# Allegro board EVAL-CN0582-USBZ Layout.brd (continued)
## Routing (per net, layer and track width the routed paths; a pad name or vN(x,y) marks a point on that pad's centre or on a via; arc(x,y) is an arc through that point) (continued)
P5V_SUPPLY: length 73.1
  TOP w0.305: A8.7 73.53,98.23 73.08,97.78 C213.1 ; R228.1 v1(101.85,99.82) ; U32.2 86.54,96.72 C239.1 ; A5.7 v1(99.06,91.51) ; A14.7 v1(98.95,96.72) ; R310.1 C239.1 ; C239.1 v1(85.7,96.77) ; C182.1 72.96,89.97 A7.7
  TOP w0.508: C182.1 C183.2 v1(70.99,89.91) ; v1(71.13,97.78) C215.2 C213.1 ; v1(38.67,60.01) v1(37.97,60.01) 37.98,60 R8.1
  L3_SIG w0.508: 38.23,60.96 38.23,60.26 v1(37.97,60.01) 37.97,60.71 38.23,60.96 ; 38.23,60.96 38.61,61.34 ; 38.61,61.34 38.61,60.07 v1(38.67,60.01) ; 38.61,61.34 38.61,64.64 39.37,65.4 39.37,70.99 41.53,73.15 46.4,73.15 48.01,74.76 48.01,82.93 53.47,88.39 53.47,96.69 53.42,96.74 53.42,100.41 v1(54.23,101.22)
  BOTTOM w0.305: v1(98.95,96.72) 99.01,96.77 C235.1 C237.2 v1(99.7,98.54) ; v1(99.06,91.51) 99.12,91.51 99.18,91.57 C190.2 C187.1
  vias: v1(54.23,101.98) v1(54.99,101.98) v1(54.99,101.22)
V1P2_SUPPLY: length 30.1
  TOP w0.203: R225.1 31.79,14.44 31.8,14.43 ; U1.H1 47.1,16.15 v2(47.24,16) ; U1.F11 45.34,24.94 45.34,25.4 v2(44.96,25.78) ; U1.C3 v2(42.68,17.97) ; 32.16,14.2 32.18,14.17 33.17,14.17 33.32,14.33 33.32,16.76 32.65,17.44 R226.2 ; v1(48.39,25.78) 47.91,25.3 47.91,24.8 U1.J11 ; U1.L5 49.54,19.94 v2(50.44,19.94) ; U1.E9 v2(44.28,23.6) ; U1.B10 v2(41.88,24.4) ; U1.L7 v2(50.16,21.59)
  TOP w0.508: E9.2 31.11,21.59 v1(30.99,21.46) ; C138.2 v1(52.58,17.58) ; C22.1 v1(50.56,27.3) ; C136.1 v1(47.48,14.23) ; v1(52.45,14.48) 52.46,14.49 C20.2 ; v1(44.83,27.05) 44.56,27.33 44.54,27.33 44.28,27.58 44.28,27.6 43.82,28.07 C18.2 ; v1(52.58,18.6) 53.32,18.6 C24.1 ; C21.2 v1(40.01,25.91) ; C19.1 v1(40.01,26.92) ; E8.2 v1(34.8,13.59)
  BOTTOM w0.305: v2(44.28,23.6) 44.28,24.43 C135.1
  BOTTOM w0.457: C23.2 46.98,16.12 47.1,16 v2(47.24,16)
  BOTTOM w0.508: E6.2 31.5,20.96 v1(30.99,21.46) ; C139.1 v1(39.37,15.11)
  vias: v1(31.6,13.18) v1(31.6,12.55) v1(31.62,11.89)
3P3V_SUPPLY: length 265.2
  TOP w0.152: v1(9.27,8.76) 9.27,8.76
  TOP w0.203: U1.C11 v2(42.68,25.2) ; U1.H11 47.1,25.89 v1(47.37,26.16) ; U1.F1 45.5,16.09 v2(45.41,16) ; 50.74,23.19 U1.L9 ; U1.B1 v2(41.88,16.37) ; R111.2 v1(7.38,63.5) ; U1.E3 v2(45.11,18.8)
  TOP w0.305: v1(68.96,43.05) 68.96,42.93 69.46,42.43 C281.1 69.6,42.15 U39.1 ; R247.2 38.47,68.97 38.75,68.7 U12.2 ; v1(29.57,35.43) 29.59,35.43 29.85,35.17 C294.1 30.36,35.18 U42.5 ; 50.74,23.19 50.75,23.18 v1(51.12,23.18)
  TOP w0.406: v1(13.84,89.42) C274.1 12.96,89.53 U37.2
  TOP w0.508: v1(53.6,2.42) R192.2 R191.2 ; R337.2 v1(11.68,91.44) ; R246.2 v1(35.92,67.94) ; v1(19.06,94.48) C273.1 C288.2 16.85,94.65 Y6.4 ; R315.2 v1(13.09,80.77) ; v1(13.09,82.8) C245.1 12.25,82.86 U33.5 ; 56.91,27.17 P8.3 ; P8.3 57.53,25.04 ; P8.3 57.53,29.29 ; U2.8 53.97,34.33 C205.1 v1(54.99,33.27) ; R355.2 58.17,45.58 58.25,45.5 58.25,44.93 58.25,44.92 58.25,44.88 v1(58.04,44.68) ; v1(20.19,13.97) 20.19,13.97 19.99,13.77 19.99,13.58 19.94,13.53 R196.2 ; R284.1 v1(91.29,10.08) ; R207.2 v1(23.11,1.02) ; 12.86,19.01 E15.2 ; E15.2 14.82,19.01 ; E15.2 13.84,19.86 ; R194.2 v1(64.9,36.7) ; R236.2 v1(30.92,10.79) R206.2 ; 14.87,18.96 C277.1 ; C277.1 16.37,18.96 ; C277.1 15.62,19.69 ; R89.2 22.22,100.2 v1(22.22,101.09) ; C144.1 C148.2 47.51,26.3 v1(47.37,26.16) ; R237.1 R238.1 v1(35.19,10.79) ; R193.2 v1(64.9,34.42) ; v1(56.01,21.84) 55.88,21.84 55.8,21.77 55.72,21.77 55.62,21.67 55.41,21.67 55.4,21.67 54.83,21.67 54.83,21.67 R179.2 ; R356.1 v1(38.87,54.74) ; C147.1 51.68,23.74 v1(51.12,23.18) ; R229.2 v1(21.97,1.02) ; C151.1 C155.2 v2(45.41,16) ; v1(14.74,90.54) C290.2 C289.1 15.02,88.37 15.02,86.93 U41.5 ; Y4.4 Y4.1 65.57,83.81 C176.1 C267.2 v1(63.09,83.81) ; R250.1 v1(41.4,80.64) ; R197.1 v1(64.9,35.56) ; R199.2 v1(21.08,13.97) ; v1(17.95,23.41) C257.2 C258.2 17.65,26.21 C255.1 17.65,28.33 v1(17.53,28.45) ; v1(13.59,60.71) 13.84,60.45 R294.2 ; v1(8.6,76.93) C286.2 8.6,76.16 C285.1 8.58,75.07 U3.5 ; R352.1 v1(37.66,62.11) ; R210.1 v1(50.67,38.35) ; R357.2 v1(53.85,9.14) ; R244.2 v1(35.54,65.71) ; R240.2 v1(47.26,70.74) ; v1(30.23,43.43) 30.52,43.73 E16.1 ; R230.2 v1(20.83,1.01) ; R211.2 v1(50.67,37.08) ; R320.2 v1(67.69,40.39) ; R283.1 v1(91.42,31.03) ; R149.1 v1(55.38,48.64) ; v1(56.22,44.23) 56.18,44.26 56.18,44.48 55.74,44.92 R255.1 ; R279.1 v1(91.42,69.54) ; R331.2 v1(17.02,97.03) ; R313.1 v1(8.52,68.46) ; C246.2 v1(13.09,81.79) ; U38.5 5.65,85.4 5.96,85.1 C275.1 C276.2 v1(8.15,85.1) ; E17.1 v1(32.68,52.62) ; v1(47.37,68.71) 47.12,68.45 R242.2 ; 9.27,8.76 R208.1 ; R209.1 v1(50.67,35.69) ; R205.2 23.89,13.2 v1(24.38,13.69) ; v1(35.79,68.97) C16.2 R247.2 ; R200.2 v1(22.22,13.97) ; R275.2 v1(22.73,14.6) ; R280.1 v1(91.29,48.59)
  L3_SIG w0.508: v1(91.29,10.08) 90.63,10.74 90.63,17.68 92.46,19.51 92.46,20.83 91.42,21.87 v1(91.42,31.03) 91.44,31.05 91.44,35.05 90.04,36.45 90.04,43.69 91.29,44.93 v1(91.29,48.59) 91.31,48.61 91.31,54.1 92.09,54.88 92.09,59.68 91.42,60.35 v1(91.42,69.54) ; v1(39.52,27.62) 40.29,27.62 42.68,25.23 v2(42.68,25.2)
  L4_SIG w0.508: 31.62,5.68 31.62,6.86 ; 31.62,6.86 30.44,6.86 ; 31.62,6.86 31.62,8.04 ; 31.62,6.86 32.8,6.86 ; 34.63,75.82 P11.1 ; P11.1 35.81,77 ; P11.1 37,75.82 ; 35.81,79.54 P11.2 34.63,78.36 ; 39.08,4.32 40.26,4.32 ; 40.26,4.32 41.44,4.32 ; 40.26,4.32 40.26,3.14 ; 40.26,4.32 40.26,5.5 ; 45.34,6.86 46.52,6.86 ; 45.34,6.86 45.34,5.68 ; 45.34,6.86 44.16,6.86 ; 45.34,6.86 45.34,8.04 ; v1(51.12,23.18) 51.5,23.18 51.82,23.5 ; 40.01,28.7 40.01,28.24 39.52,27.76 v1(39.52,27.62) ; 47.12,29.08 47.12,26.42 v1(47.37,26.16)
  BOTTOM w0.203: v1(17.53,28.45) 17.88,28.45 18.06,28.27 U35.4 ; U36.12 11.93,22.39 12.07,22.25 12.19,22.25 C256.1
  BOTTOM w0.254: U16.9 57.72,46.23 57.69,46.2 56.9,46.2 C140.1 C143.1
  BOTTOM w0.305: C162.1 45.09,18.82 v2(45.11,18.8)
  BOTTOM w0.356: C201.2 C200.1 42.68,26.02 v2(42.68,25.2)
  BOTTOM w0.508: R100.2 v1(6.73,20.45) ; E4.2 44.74,40.17 44.58,40 v1(44.58,39.62) ; v1(54.61,46.46) 54.72,46.35 54.81,46.35 55.08,46.08 C143.1 ; R1.2 v1(14.95,23.5) ; R287.2 27.55,66.16 v1(28.83,67.44) ; C170.2 C162.1 ; E7.2 38.53,26.63 v1(39.52,27.62) ; R317.2 v1(7.5,25.59) ; v1(14.83,22.14) C259.2 13.58,21.84 C256.1 ; C197.2 41.88,16.11 v2(41.88,16.37) 41.88,17.04 C194.1 ; v1(91.29,10.08) 86.85,5.64 56.82,5.64 v1(53.6,2.42) ; E3.1 v1(46.04,48.22) ; R79.2 v1(14.95,24.64)
  vias: v1(15.11,20.83) v1(15.11,20.07) v1(16.13,20.83) v1(16.13,20.07) v1(16.89,20.07) v1(16.89,19.3) v1(56.39,29.21) v1(56.39,28.45) v1(56.39,27.81) v1(56.39,27.05) v1(56.39,26.29) v1(56.39,25.65)
10P5V_SUPPLY: length 16.3
  TOP w0.152: TP49.1 39.5,101.35 39.5,101.3 v1(39.54,101.3)
  TOP w0.508: R97.2 v1(27.93,99.81)
  BOTTOM w0.305: v1(39.54,101.3) 38.48,102.36 28.24,102.36 27.93,102.06 v1(27.93,99.81)
4332_A: length 5.9
  TOP w0.203: P11.5 40.27,75.19 R252.1 40.65,73.15 U12.20
4332_B: length 9
  TOP w0.203: U12.19 41.15,73.42 R252.2 41.27,73.78 42.16,74.68 42.16,77.09 P11.6
4332_CS: length 64.2
  TOP w0.203: v1(42.67,61.85) 42.41,62.11 R245.1
  L3_SIG w0.152: v1(42.67,61.85) 41.15,60.32 41.15,52.46 42.83,50.77 43.17,50.77 44.42,49.52 44.42,47.52 42.92,46.02 41.16,46.02 41,45.86 41,44.26 48.01,37.25 48.01,35.36 52.98,30.39 52.98,29.1 54.89,27.19 54.89,24.89 55.28,24.5 55.28,21.1 56.08,20.29 56.54,20.29 57.56,19.28 57.56,15.94 57.4,15.79 v1(57.4,14.99)
  BOTTOM w0.152: R214.2 55.37,14.99 v1(57.4,14.99)
4332_EN: length 110.2
  TOP w0.203: R353.2 R246.1 37.93,68.16 v1(38.48,68.16) 39.48,68.16 U12.3
  L3_SIG w0.152: v1(33.53,58.67) 33.15,58.67 24.26,49.78 24.26,43.05 27.56,39.75 27.56,33.53 26.16,32.13 25.7,32.13 25.15,31.58 25.15,31.12 24.13,30.1 24.13,28.58 21.41,25.86 21.41,24.12 19.88,22.58 19.88,15.3 17.48,12.9 17.48,3.23 18.03,2.67 27.43,2.67 30.35,5.59 30.35,7.62 34.42,11.68 36.62,11.68 37.13,12.19 38.23,12.19 v1(38.73,11.68)
  BOTTOM w0.152: TP30.1 38.73,9.27 v1(38.73,11.68) 39.03,11.98 R270.2
  BOTTOM w0.203: v1(33.53,58.67) 33.53,59.94 37.85,64.26 37.85,67.53 v1(38.48,68.16)
4332_GPIO1: length 83.5
  TOP w0.203: U12.11 43.3,61.72 42.89,61.32 37.24,61.32 v1(36.96,61.04)
  L3_SIG w0.152: v1(45.87,11.68) 46.4,12.22 47.3,12.22 47.6,12.52 50.78,12.52 51.22,12.96 53.18,12.96 56.57,16.35 56.57,18.87 56.13,19.3 55.63,19.3 54.28,20.65 54.28,24.09 53.9,24.48 53.9,26.78 51.54,29.14 50.94,29.14 49.78,30.3 49.78,30.48 49.28,30.99 48.64,30.99 47.75,30.1 45.65,30.1 42.13,33.62 42.13,36.31 38.68,39.76 38.68,47.24 39.62,48.18 39.62,57.4 38.85,58.18 38.3,58.18 36.45,60.03 36.45,60.54 36.95,61.04 v1(36.96,61.04)
  BOTTOM w0.152: R215.2 45.87,12.01 v1(45.87,11.68)
4332_GPIO2: length 80.3
  TOP w0.152: v1(46.59,11.62) 46.59,12.3 R216.2
  TOP w0.203: U12.12 v1(44.18,67.19)
  L3_SIG w0.152: v1(44.18,67.19) 44.18,64.59 40.49,60.89 40.49,52.18 42.55,50.11 42.89,50.11 43.76,49.24 43.76,47.8 42.65,46.68 40.85,46.68 40.34,46.17 40.34,43.97 43.56,40.74 43.56,38.69 43.61,38.64 43.61,38.38 44.1,37.89 44.23,37.89 44.74,37.38 44.8,37.38 51.44,30.75 51.44,30.18 54.56,27.06 54.56,24.75 54.95,24.37 54.95,20.96 55.94,19.96 56.41,19.96 57.23,19.15 57.23,16.08 56.9,15.75 56.9,14.22 56.13,13.46 56.13,12.62 54.97,11.46 48.9,11.46 48.16,12.19 47.74,12.19 47.17,11.62 v1(46.59,11.62)
4332_GPIO3: length 82.2
  TOP w0.203: U12.13 43.33,67.73 44.41,67.73 44.83,67.31 44.83,62.71 43.05,60.93 37.69,60.93 37.08,60.32 v1(36.96,60.32)
  L3_SIG w0.152: v1(51.43,12.45) 51.57,12.32 53,12.32 56.9,16.21 56.9,19.01 56.27,19.63 55.81,19.63 54.61,20.83 54.61,24.23 54.23,24.62 54.23,26.92 51.07,30.08 51.07,30.65 44.66,37.05 44.6,37.05 44.09,37.56 43.97,37.56 43.28,38.25 43.28,38.51 43.23,38.56 43.23,39.36 40.01,42.59 40.01,46.31 40.71,47.01 42.51,47.01 43.43,47.93 43.43,49.11 42.76,49.78 42.42,49.78 40.16,52.04 40.16,57.34 38.99,58.51 38.65,58.51 36.96,60.2 v1(36.96,60.32)
  BOTTOM w0.203: R217.2 v1(51.43,12.45)
4332_INT: length 1.5
  TOP w0.203: R248.1 42.15,64.27 U12.10
4332_Y: length 12.7
  TOP w0.203: U12.17 42.53,70.34 45.23,73.04 45.23,74.7 44.7,75.22 44.7,77.09 P11.8 43.17,78.62 R250.2
4332_Z: length 6.2
  TOP w0.203: P11.7 43.06,75.45 R251.1 43.06,72.78 41.66,71.37 41.66,70.34 U12.18
7768_VCM: length 21.6
  TOP w0.203: 53.21,49.64 U18.59
  TOP w0.508: R117.1 v1(65.78,61.36) ; 53.21,49.64 53.74,50.16 55.12,50.16 57.51,52.55 v1(58.65,52.55)
  L3_SIG w0.508: v1(65.78,61.36) 64.9,60.49 64.9,58.05 59.41,52.55 v1(58.65,52.55)
-10P5_SUPPLY: length 18.9
  TOP w0.508: R95.2 v1(24.76,84.96)
  BOTTOM w0.305: v1(41.28,88.9) 30.99,88.9 28.63,86.54 26.34,86.54 v1(24.76,84.96)
AC_WAVE_SIGNAL: length 26.6
  TOP w0.305: A7.6 73.33,90.62 TP31.1 v1(71.75,91.19) ; U20.4 v1(78.02,95.34) ; R156.2 v1(82.43,89.79)
  L3_SIG w0.305: v1(82.43,89.79) 81.03,91.19 v1(71.75,91.19) 71.75,92.71 74.38,95.34 v1(78.02,95.34)
  BOTTOM w0.305: C292.2 82.05,89.41 v1(82.43,89.79)
AD5543_CS: length 82.4
  TOP w0.203: U20.8 75.04,93.39 75.69,92.74 75.69,86.73 76.07,86.35 v1(76.07,82.8) ; v1(60.45,30.84) 60.14,30.53 55.93,30.53 54.48,29.08 R133.1
  L3_SIG w0.152: v1(60.45,30.84) 59.36,31.93 59.36,45.12 58.34,46.13 58.34,46.41 58.34,49.13 57.48,50 57.48,53.05 59.38,54.94 60.15,54.94 61.44,56.24 61.44,71.6 70.36,80.52 73.79,80.52 v1(76.07,82.8)
AD5686_GAIN: length 25
  TOP w0.152: v1(48.51,40.72) 51.21,40.72 53.99,43.5 56.91,43.5 57.38,43.97 v1(58.04,43.97)
  BOTTOM w0.152: v1(58.04,43.97) 58.52,43.97 58.95,44.39 U16.8 ; R137.1 48.28,29.57 48.06,29.79 48.06,30.83 48.28,31.06 48.28,31.9 48.51,32.13 v1(48.51,40.72)
AD5686_LDAC: length 34.1
  L3_SIG w0.152: v1(62.48,22.48) 62.48,41.61 v1(60.27,43.81)
  BOTTOM w0.152: U16.7 59.45,44.64 v1(60.27,43.81) ; R166.1 55.28,20.32 62.48,20.32 62.59,20.42 62.59,20.42 62.99,20.82 62.99,21.98 62.49,22.48 v1(62.48,22.48)
AD5686_RSTSEL: length 40
  TOP w0.152: v1(62.38,20.93) 62.03,20.57 54.39,20.57 R144.1
  L3_SIG w0.152: v1(59.13,49.53) 63.04,45.62 63.04,21.46 62.51,20.93 v1(62.38,20.93)
  BOTTOM w0.203: U16.14 59.45,49.21 v1(59.13,49.53)
AD5686R_RST: length 39.1
  L3_SIG w0.152: v1(62.48,21.77) 62.28,21.97 62.27,21.97 61.98,22.27 61.98,23.35 60.1,25.23 60.1,30.42 59.03,31.49 59.03,44.98 58.01,46 58.01,48.25 v1(57.67,48.6)
  BOTTOM w0.152: R146.1 55.96,25.15 57.4,25.15 60.78,21.77 v1(62.48,21.77)
  BOTTOM w0.203: U16.13 57.82,48.48 57.7,48.6 v1(57.67,48.6)
AD5686R_SYNC: length 24.2
  TOP w0.152: v1(57.3,47.35) 57.31,47.36 R355.1
  L3_SIG w0.152: v1(57.3,47.35) 57.3,46.21 58.67,44.83 58.67,33.4 v1(58.42,33.15)
  BOTTOM w0.152: v1(58.42,33.15) 55.88,30.61 55.88,27.61 R136.1
  BOTTOM w0.203: v1(57.3,47.35) 57.38,47.35 57.5,47.23 U16.11
AD7768_CS: length 44.8
  TOP w0.152: U18.16 42.1,54.8 41.91,54.99 40.26,54.99 39.87,55.38 R356.2 ; R134.1 55.11,24.77 56.01,23.88 56.96,23.88 v1(57.4,23.43)
  TOP w0.203: U18.16 v1(42.1,52.78)
  L3_SIG w0.152: v1(57.4,23.43) 57.23,23.61 57.23,24.42 57.12,24.52 57.12,29.19 56.39,29.93 55.88,29.93 51.18,34.63 51.18,36.07 50.67,36.58 50.42,36.58 49.78,37.21 49.78,38.4 44.96,43.23 44.96,46.9 45.09,47.02 45.09,49.79 v1(42.1,52.78)
AD7768_DCLK: length 37
  TOP w0.203: U18.28 41.2,46.64 41.23,46.6 43.44,46.6 v1(44.45,45.59)
  L3_SIG w0.152: v1(44.45,45.59) 44.45,43.27 49.4,38.31 49.4,35.94 55.88,29.46 55.88,25.3 56.9,24.28 56.9,22.1 v1(57.15,21.84)
  BOTTOM w0.152: v1(57.15,21.84) 57.53,22.23 TP40.1 57.49,22.56 R140.1
AD7768_DRDY: length 38.7
  TOP w0.152: R141.1 55.45,22.72 55.8,23.07 55.84,23.07 55.88,23.11 v1(56.01,23.11)
  TOP w0.203: U18.29 41.87,46.14 v1(42.55,45.47) 42.55,44.51 41.22,43.18 TP39.1
  L3_SIG w0.152: v1(56.01,23.11) 55.61,23.52 55.61,24.64 55.22,25.03 55.22,29.14 48.73,35.64 48.73,38.05 43.6,43.18 43.6,44.53 42.67,45.47 v1(42.55,45.47)
AD7768_FILTER: length 2.9
  TOP w0.152: U18.11 44.6,55.13 44.6,55.13 44.6,55.4 45.47,56.26 R259.2
AD7768_FORMAT0: length 2.3
  TOP w0.203: U18.56 52.57,48.14 52.83,47.88
  TOP w0.254: R257.2 53.33,47.38 52.83,47.88
AD7768_MODE0: length 2.7
  TOP w0.203: U18.12 44.1,55.63 44.32,55.85 R263.2
AD7768_MODE1: length 2.8
  TOP w0.152: R262.2 43.18,55.54 43.6,55.13 U18.13
AD7768_MODE2: length 3
  TOP w0.203: U18.14 43.1,55.07 42.04,56.13 R261.2
AD7768_MODE3: length 3.8
  TOP w0.152: U18.15 42.6,54.94 42.17,55.37 41.28,55.37 40.89,55.75 R260.2
AD7768_RST: length 25.3
  TOP w0.203: v1(41.55,45.36) 41.51,45.36 41.23,45.64 U18.30
  L3_SIG w0.152: v1(53.54,30.1) 53.54,30.29 48.36,35.48 48.36,37.8 42.29,43.87 42.29,44.62 v1(41.55,45.36)
  BOTTOM w0.152: R147.1 55.24,29.85 54.99,30.1 53.55,30.1 v1(53.54,30.1)
AD7768_START: length 38.3
  TOP w0.203: U18.37 44.1,44.49 45.35,45.74 v1(46.5,45.74)
  L3_SIG w0.152: v1(58.67,22.23) 58.67,23.38 57.79,24.27 57.79,29.47 56.66,30.59 56.16,30.59 54.1,32.65 54.1,38.14 v1(46.5,45.74)
  BOTTOM w0.152: R152.1 56.81,23.66 57.09,23.94 57.85,23.94 58.67,23.11 v1(58.67,22.23)
AD9833_FSYNC: length 79.8
  TOP w0.203: v1(80.14,83.95) U19.8 ; v1(60.6,30.15) 60.5,30.05 56.21,30.05 54.35,28.19 R130.1
  L3_SIG w0.152: v1(80.14,83.95) 80.14,82.55 77.77,80.19 70.54,80.19 61.77,71.43 61.77,56.1 60.28,54.61 59.51,54.61 57.81,52.91 57.81,50.13 58.67,49.27 58.67,46.27 59.69,45.26 59.69,32.38 60.96,31.12 60.96,30.5 v1(60.6,30.15)
ADC_REF: length 20.9
  TOP w0.254: 47.1,55.34 U18.6 47.1,53.07 46.86,52.84 46.86,51.94 47.37,51.43 47.37,44.96 47.1,44.68 U18.43
  TOP w0.305: 47.1,55.34 47.1,55.63
  TOP w0.508: C157.2 48.32,59.22 VREF.1 ; C157.2 48.62,57.84 R139.2 R138.2 ; C157.2 48.32,57.72 47.89,57.28 R88.2 47.1,55.98 47.1,55.63
ADP5071_EN: length 119.5
  TOP w0.152: R126.1 51.58,29.74 51.94,30.1 v1(51.94,30.71) ; v1(25.65,91.32) 25.64,91.31 R98.2 20.82,91.31 20.19,90.68 20.19,88.77 v1(19.94,88.52)
  TOP w0.203: v1(26.04,94.72) 26.3,94.98 U15.9 26.3,97.21 26.1,97.41 23.49,97.41 22.61,98.3 R89.1 ; U15.11 v1(25.65,91.32)
  L3_SIG w0.152: v1(48.9,82.17) 49.28,81.79 49.28,75.31 45.47,71.5 45.47,67.76 44.58,66.87 44.58,64.52 40.82,60.76 40.82,52.32 42.69,50.44 43.03,50.44 44.09,49.38 44.09,47.66 42.79,46.35 40.98,46.35 40.67,46.03 40.67,44.1 43.89,40.88 43.89,38.83 43.94,38.78 43.94,38.52 44.24,38.22 44.37,38.22 44.87,37.71 44.94,37.71 v1(51.94,30.71)
  L3_SIG w0.203: v1(25.65,91.32) 25.65,94.33 v1(26.04,94.72)
  BOTTOM w0.152: v1(19.94,88.52) 19.94,84.84 21.84,82.93 48.13,82.93 v1(48.9,82.17)
ADP7142_ADJ: length 3.8
  TOP w0.203: R81.2 34.78,73.67 R277.1 33.73,73.65 R80.1 32.51,73.78 U11.2
BNC_CTRL: length 133.8
  TOP w0.305: U32.8 v1(89.45,97.37)
  L3_SIG w0.152: v1(40.17,10.45) 40.59,10.03 41.77,10.03 42.81,11.07 55.48,11.07 58.83,14.42 58.83,17.96 59.61,18.75 59.61,23.38 58.45,24.55 58.45,29.74 56.52,31.67 56.52,38.59 54.1,41.01 54.1,49.02 55.5,50.42 55.5,56.26 57.91,58.67 57.91,72.01 68.46,82.56 71.45,82.56 74.11,85.22 79.29,85.22 79.93,84.58 80.35,84.58 80.98,85.22 86.94,85.22 89.59,87.86 89.59,97.23 v1(89.45,97.37)
  BOTTOM w0.152: R273.2 v1(40.17,10.45)
CH0_COUP_OPT: length 129.4
  TOP w0.305: U22.15 v1(95.36,70.02) ; U22.6 v1(95.36,75.67)
  L3_SIG w0.152: v1(46.74,9.14) 47.75,9.14 47.88,9.02 53.29,9.02 53.34,8.97 53.34,8.93 53.64,8.64 54.06,8.64 54.36,8.93 54.36,8.97 54.41,9.02 77.72,9.02 83.69,3.05 88.14,3.05 92.58,7.49 92.58,16 94.49,17.91 94.49,30.1 93.22,31.37 93.22,55.63 95.12,57.53 95.12,69.78 v1(95.36,70.02)
  BOTTOM w0.152: v1(46.74,9.14) 47.11,9.52 47.11,11.82 46.78,12.15 46.77,12.15 R218.2
  BOTTOM w0.203: v1(95.36,70.02) 94.32,70.02 93.47,70.87 93.47,75.06 94.09,75.67 v1(95.36,75.67)
CH0_COUPLED: length 24.5
  TOP w0.203: U22.16 96.01,70.26 96.14,70.13 v1(96.14,70.02) ; U22.9 93.08,73.82 v1(92.2,73.82) R53.1
  TOP w0.305: v1(101.73,73.02) 101.6,73.15 C119.1
  BOTTOM w0.305: v1(101.73,73.02) 101.09,73.02 97.66,76.45 93.34,76.45 92.2,75.31 v1(92.2,73.82) 92.2,71.5 94.33,69.37 95.63,69.37 96.07,69.81 96.07,69.95 v1(96.14,70.02)
CH0_G0: length 42.7
  TOP w0.203: A10.5 v1(82.16,77.98)
  BOTTOM w0.203: v1(82.16,77.98) 81.61,78.54 73.61,78.54 69.14,74.07 69.14,54.37 70.76,52.75 71.86,52.75 73.43,51.18 U40.4
CH0_G1: length 44.9
  TOP w0.203: A10.6 80.78,77.33 v1(80.77,77.34)
  BOTTOM w0.203: U40.5 74.08,50.84 74.54,51.3 74.77,51.3 75.09,51.62 75.09,52.82 74.78,53.14 70.92,53.14 69.52,54.53 69.52,73.91 73.77,78.16 79.96,78.16 v1(80.77,77.34)
CH0_G2: length 43.6
  TOP w0.203: v1(82.04,76.73) 82.09,76.68 A10.7
  BOTTOM w0.203: v1(82.04,76.73) 81.89,76.58 80.52,76.58 79.32,77.77 73.93,77.77 69.9,73.75 69.9,55.87 72.25,53.52 74.94,53.52 75.47,52.98 75.47,51.46 74.73,50.72 U40.6
CH0_OUT_N: length 36.3
  TOP w0.203: C85.2 C83.2 ; C83.2 67.93,72.29 R73.2 ; C83.2 v1(66.95,72.27) TP14.1 ; v1(50.16,51.43) 50.17,51.43 50.33,51.43 50.53,51.64 U18.63
  BOTTOM w0.152: v1(66.95,72.27) 65.82,72.27 50.55,56.99 50.55,53.72 51.57,52.7 51.57,51.96 51.22,51.62 50.83,51.62 50.64,51.43 v1(50.16,51.43)
CH0_OUT_P: length 36.7
  TOP w0.203: C83.1 67.96,73.82 R74.2 ; C83.1 C86.2 ; C83.1 v1(66.95,73.87) TP15.1 ; U18.64 v1(50.16,52.14)
  BOTTOM w0.152: v1(66.95,73.87) 50.22,57.13 50.22,53.58 51.24,52.56 51.24,52.1 51.09,51.95 50.83,51.95 50.64,52.14 v1(50.16,52.14)
CH0_SHIFT: length 53.3
  TOP w0.406: A3.3 v1(86.76,75.41)
  BOTTOM w0.203: v1(86.76,75.41) 86.81,75.37 C263.1 87.73,75.34 87.73,73.86 88.66,72.93 88.66,47.52 87.4,46.25 71.58,46.25 69.83,48 C6.2 67.95,47.99 R2.2
CH0_VOCM: length 30.7
  TOP w0.203: A17.1 85.79,68.63 85.99,68.83 87.11,68.83 87.69,69.42 A17.4 87.69,71.69 v1(87.63,71.75) 87.63,71.88 87.29,72.22 R59.1 ; U9.9 v1(72.67,74.41)
  BOTTOM w0.203: v1(72.67,74.41) 74.58,74.41 79.37,69.63 85.5,69.63 v1(87.63,71.75) 86.74,72.64 84.58,72.64 83.57,73.66 R298.2
CH1_COUP_OPT: length 109.6
  TOP w0.152: R272.2 44.96,11.05 45.09,10.92 v1(45.09,9.14)
  TOP w0.305: U27.15 v1(95.23,49.06) ; U27.6 v1(95.23,54.72)
  L3_SIG w0.152: v1(95.23,49.06) 93.6,47.43 93.6,31.62 94.87,30.35 94.87,17.78 92.91,15.82 92.91,9.9 92.91,7.36 88.27,2.72 83.56,2.72 77.64,8.64 54.53,8.64 54.2,8.31 53.5,8.31 53.17,8.64 45.59,8.64 v1(45.09,9.14)
  BOTTOM w0.203: v1(95.23,49.06) 94.19,49.06 92.96,50.29 92.96,53.72 93.96,54.72 v1(95.23,54.72)
CH1_COUPLED: length 24.5
  TOP w0.203: U27.16 95.88,49.08 v1(95.94,49.02) ; C120.1 101.59,52.25 101.65,52.2 v1(101.73,52.2) ; R54.1 v1(92.08,52.86) 92.96,52.86 U27.9
  BOTTOM w0.305: v1(95.94,49.02) 95.94,48.57 95.69,48.32 94.05,48.32 92.08,50.29 v1(92.08,52.86) 92.08,53.92 93.45,55.3 96.47,55.3 99.57,52.2 v1(101.73,52.2)
CH1_G0: length 16.2
  TOP w0.203: v1(81.79,57.43) 82.14,57.08 82.29,57.08 82.34,57.03 A11.5
  L3_SIG w0.203: v1(75.38,48.19) 75.38,49.7 75.47,49.79 75.47,53.25 79.63,57.4 81.76,57.4 v1(81.79,57.43)
  BOTTOM w0.203: U40.7 v1(75.38,48.19)
CH1_G1: length 14.9
  TOP w0.203: v1(81.47,56.8) 81.66,56.8 81.76,56.7 82.14,56.7 82.45,56.38 A11.6
  L3_SIG w0.203: v1(76.07,48.39) 76.07,53.09 79.88,56.9 81.37,56.9 v1(81.47,56.8)
  BOTTOM w0.203: v1(76.07,48.39) 76.03,48.43 U40.8
CH1_G2: length 14.7
  TOP w0.203: v1(81.92,56.16) 82.35,55.73 A11.7
  L3_SIG w0.203: v1(81.92,56.16) 81.82,56.26 80.14,56.26 76.68,52.81 v1(76.68,48.01)
  BOTTOM w0.203: v1(76.68,48.01) U40.9
CH1_OUT_N: length 26.1
  TOP w0.152: TP16.1 v1(66.83,51.31)
  TOP w0.203: C84.2 v1(66.83,51.31) ; C84.2 67.81,51.34 R75.2 ; C84.2 C87.2 ; U18.1 49.6,55.05 49.52,55.13 49.52,55.35 49.67,55.5 49.89,55.5 50.16,55.22 50.16,54.97 50.37,54.76 50.51,54.62 51.05,54.62 51.21,54.46 v1(51.71,54.46)
  BOTTOM w0.152: v1(66.83,51.31) 65.38,52.76 65.38,53.41 64.13,54.66 51.91,54.66 v1(51.71,54.46)
CH1_OUT_P: length 26.4
  TOP w0.152: TP17.1 v1(66.83,52.91)
  TOP w0.203: R76.2 67.83,52.86 C84.1 ; C84.1 v1(66.83,52.91) ; C84.1 C88.2 ; v1(51.69,55.17) 51.22,55.17 51.05,55 50.67,55 50.64,55.03 50.55,55.12 50.55,55.38 50.04,55.88 49.51,55.88 49.14,55.5 49.14,55.11 49.1,55.07 U18.2
  BOTTOM w0.152: v1(51.69,55.17) 51.87,54.99 64.26,54.99 65.71,53.54 65.71,52.9 65.91,52.7 66.67,52.7 66.83,52.86 v1(66.83,52.91)
CH1_SHIFT: length 31.8
  TOP w0.305: A4.3 v1(86.64,54.45)
  BOTTOM w0.203: v1(86.64,54.45) 87.59,54.45 C264.1 87.63,53.47 88.27,52.83 88.27,48.26 87,46.99 72.01,46.99 68.59,50.41 C11.2 67.95,50.41 R5.2
CH1_VOCM: length 31.1
  TOP w0.203: R60.1 87.17,51.26 87.63,50.8 v1(87.63,50.67) 87.69,50.61 A16.4 87.69,48.34 87.11,47.75 85.99,47.75 85.79,47.55 A16.1 ; U10.9 v1(72.54,54.05)
  BOTTOM w0.203: R299.2 83.44,52.2 83.82,51.82 87.12,51.82 87.63,51.31 v1(87.63,50.67) 87.5,50.55 80.01,50.55 76.56,53.99 74.64,53.99 74.58,54.05 v1(72.54,54.05)
CH2_COUP_OPT: length 93.4
  TOP w0.305: U28.6 v1(95.36,37.16) ; U28.15 v1(95.36,31.51)
  L3_SIG w0.152: v1(44.37,9.14) 44.37,8.58 44.65,8.31 53.03,8.31 53.36,7.98 54.33,7.98 54.66,8.31 77.5,8.31 83.42,2.39 88.41,2.39 93.24,7.22 93.24,9.76 93.24,15.69 95.25,17.69 95.25,31.4 v1(95.36,31.51)
  BOTTOM w0.152: R232.2 44.37,9.98 44.37,9.98 v1(44.37,9.14)
  BOTTOM w0.203: v1(95.36,37.16) 94.09,37.16 93.09,36.16 93.09,32.74 94.32,31.51 v1(95.36,31.51)
CH2_COUPLED: length 24.4
  TOP w0.203: R19.1 v1(92.2,35.31) 93.08,35.31 U28.9 ; C131.1 v1(101.73,34.67) ; v1(96.14,31.51) 96.14,31.62 96.01,31.75 U28.16
  BOTTOM w0.305: v1(96.14,31.51) 96.07,31.44 96.07,31.3 95.63,30.86 94.08,30.86 92.2,32.74 v1(92.2,35.31) 92.2,36.2 94.11,38.1 96.9,38.1 100.33,34.67 v1(101.73,34.67)
CH2_G0: length 13.4
  TOP w0.203: A12.5 v1(82.16,39.47)
  L3_SIG w0.203: v1(82.16,39.47) 82.16,42.04 77.39,46.81 v1(77.39,48.01)
  BOTTOM w0.203: v1(77.39,48.01) 77.33,48.07 U40.10
CH2_G1: length 15.3
  TOP w0.203: A12.6 v1(81.79,38.82)
  L3_SIG w0.203: v1(81.79,38.82) 82.53,38.82 82.8,39.1 82.8,42.06 78.11,46.76 v1(78.11,48.26)
  BOTTOM w0.203: v1(78.11,48.26) 77.98,48.38 U40.11
CH2_G2: length 10.1
  TOP w0.203: A12.7 v1(82.16,38.17)
  L3_SIG w0.203: v1(82.16,38.17) 81.68,38.17 78.63,41.22 v1(78.63,44.22)
  BOTTOM w0.203: U40.13 v1(78.63,44.22)
CH2_OUT_N: length 33.4
  TOP w0.203: C51.2 67.93,33.78 R39.2 ; C51.2 v1(66.95,33.76) TP6.1 ; C51.2 C53.2 ; U18.50 50.49,45.14 v1(50.16,45.47)
  BOTTOM w0.203: v1(66.95,33.76) 66.95,34.21 67.16,34.42 67.69,34.42 68.45,35.18 68.45,38.61 67.03,40.03 56.11,40.03 50.8,45.33 50.3,45.33 50.3,45.34 50.29,45.34 v1(50.16,45.47)
CH2_OUT_P: length 31.7
  TOP w0.203: C51.1 v1(66.95,35.36) TP8.1 ; C51.1 C54.1 ; C51.1 67.96,35.31 R40.2 ; U18.49 50.2,44.64 v1(50.18,44.66)
  BOTTOM w0.203: v1(66.95,35.36) 67.42,34.89 67.62,34.89 68.07,35.34 68.07,38.45 66.87,39.65 55.95,39.65 50.65,44.95 50.46,44.95 v1(50.18,44.66)
CH2_SHIFT: length 29.6
  TOP w0.406: A1.3 v1(86.76,36.9)
  BOTTOM w0.203: v1(86.76,36.9) 86.81,36.85 C265.1 88.42,36.85 88.9,37.34 88.9,38.73 82.05,45.59 C7.2 67.95,45.58 R3.2
CH2_VOCM: length 30.5
  TOP w0.203: R25.1 87.29,33.71 87.76,33.24 v1(87.76,33.12) 87.82,33.06 A18.4 87.82,30.78 87.26,30.23 86.12,30.23 85.92,30.02 A18.1 ; U21.9 v1(72.67,35.9)
  BOTTOM w0.203: R300.2 83.57,35.31 84.96,33.91 87.4,33.91 87.76,33.55 v1(87.76,33.12) 87.76,32.6 87.55,32.4 79.13,32.4 75.63,35.9 v1(72.67,35.9)
CH3_COUP_OPT: length 74.5
  TOP w0.152: R233.2 43.78,10.51 43.69,10.41 43.69,9.17 v1(43.66,9.14)
  TOP w0.305: U29.15 v1(95.23,10.55) ; U29.6 v1(95.23,16.2)
  L3_SIG w0.152: v1(43.66,9.14) 43.66,8.41 44.09,7.98 52.9,7.98 53.09,7.79 53.09,7.03 53.38,6.73 53.8,6.73 54.1,7.03 54.1,7.45 54.3,7.65 54.47,7.65 54.8,7.98 77.36,7.98 83.28,2.06 88.55,2.06 93.57,7.08 93.57,7.46 93.57,8.89 v1(95.23,10.55)
  BOTTOM w0.203: v1(95.23,16.2) 93.96,16.2 92.96,15.21 92.96,11.78 94.19,10.55 v1(95.23,10.55)
CH3_COUPLED: length 24.4
  TOP w0.203: R20.1 v1(92.08,14.35) 92.96,14.35 U29.9
  TOP w0.305: v1(95.94,10.51) 95.88,10.57 U29.16 ; C153.1 v1(101.6,13.64)
  BOTTOM w0.305: v1(95.94,10.51) 95.94,10.06 95.69,9.8 94.05,9.8 92.08,11.78 v1(92.08,14.35) 92.08,15.41 93.45,16.79 96.31,16.79 99.38,13.72 101.52,13.72 v1(101.6,13.64)
CH3_G0: length 26.9
  TOP w0.203: v1(81.79,18.92) 82.17,18.92 82.42,18.67 82.46,18.67 82.61,18.52 A13.5
  L3_SIG w0.203: v1(77.98,41.4) 77.98,22.73 v1(81.79,18.92)
  BOTTOM w0.203: U40.14 v1(77.98,41.4)
CH3_G1: length 28
  TOP w0.203: A13.6 82.86,18.03 82.38,18.03 82.13,18.29 v1(81.47,18.29)
  L3_SIG w0.203: v1(81.47,18.29) 77.33,22.42 v1(77.33,41.02)
  BOTTOM w0.203: U40.15 v1(77.33,41.02)
CH3_G2: length 29.1
  TOP w0.203: A13.7 82.35,17.22 v1(81.92,17.65)
  L3_SIG w0.203: v1(81.92,17.65) 81.15,17.65 76.68,22.12 v1(76.68,41.4)
  BOTTOM w0.203: U40.16 v1(76.68,41.4)
CH3_OUT_N: length 50
  TOP w0.203: C52.2 v1(66.83,12.8) TP9.1 ; C52.2 67.81,12.83 R41.2 ; C52.2 C55.2 ; v1(49.78,44.07) 49.78,43.93 49.6,43.74 U18.48
  BOTTOM w0.203: v1(66.83,12.8) 66.83,13.21 67.03,13.41 67.54,13.41 68.45,14.33 68.45,28.94 61.04,36.35 55.37,36.35 49.53,42.19 49.53,43.34 49.78,43.59 v1(49.78,44.07)
CH3_OUT_P: length 49.3
  TOP w0.203: v1(48.9,44.07) 49.1,43.87 U18.47 ; C52.1 67.83,14.35 R42.2 ; C52.1 C56.2 ; C52.1 v1(66.83,14.4) TP10.1
  BOTTOM w0.203: v1(48.9,44.07) 48.9,43.59 49.15,43.34 49.15,42.03 55.21,35.97 60.88,35.97 68.07,28.78 68.07,14.48 67.38,13.79 67.03,13.79 66.83,14 v1(66.83,14.4)
CH3_SHIFT: length 43.1
  TOP w0.305: A2.3 v1(86.64,15.94)
  BOTTOM w0.203: R4.2 67.95,43.29 C10.2 67.95,42.66 68.86,41.76 68.86,39.8 69.72,38.94 69.72,30.86 80.7,19.89 86.46,19.89 88.44,17.91 88.44,16.1 88.24,15.9 C266.1 87.59,15.94 v1(86.64,15.94)
CH3_VOCM: length 31.3
  TOP w0.203: U6.9 v1(72.54,14.95) ; A19.1 85.79,9.07 85.99,9.27 87.14,9.27 87.69,9.82 A19.4 87.69,12.1 v1(87.63,12.16) 87.63,12.29 87.17,12.75 R26.1
  BOTTOM w0.203: v1(72.54,14.95) 75.81,14.95 80.47,10.29 84.33,10.29 85.6,11.56 87.03,11.56 v1(87.63,12.16) 86.96,12.83 84.33,12.83 83.44,13.72 R301.2
CH_FDA_DIS: length 109.2
  TOP w0.203: v1(71.81,51.31) 71.86,51.36 U10.12 ; U9.12 72.61,72.26 v1(72.61,71.57) ; U21.12 72.61,33.74 v1(72.61,33.06) ; U6.12 72.48,12.79 v1(72.48,12.11)
  L3_SIG w0.203: v1(72.61,71.57) 73.03,71.15 73.03,55.63 71.81,54.41 v1(71.81,51.31) 74.3,48.81 74.3,40.14 72.01,37.85 72.01,34.16 72.61,33.57 v1(72.61,33.06) 72.64,33.02 72.64,16.9 71.75,16.01 71.75,12.83 v1(72.48,12.11)
  BOTTOM w0.203: v1(72.48,12.11) 72.07,11.69 66.43,11.69 64.77,13.35 64.77,28.12 58.55,34.34 55.1,34.34 53.01,32.25 53.01,29.46 52.62,29.08 R127.1
CH_FDA_MODE: length 112.2
  TOP w0.203: v1(74.99,36.97) 74.99,36.89 74.92,36.82 U21.5 ; v1(52.48,29.95) 52.48,29.95 52.48,29.23 R129.1 ; U9.5 74.92,75.33 74.99,75.4 v1(74.99,75.48) ; v1(74.86,16.01) 74.86,15.94 74.79,15.86 U6.5 ; U10.5 74.79,54.38 74.86,54.45 v1(74.86,54.52)
  L3_SIG w0.203: v1(74.99,75.48) 74.72,75.48 73.03,73.79 73.03,72.01 73.41,71.63 73.41,58.29 74.86,56.83 v1(74.86,54.52) 75.09,54.3 75.09,49.95 74.68,49.54 74.68,39.3 74.99,38.99 v1(74.99,36.97) 75.69,36.27 75.69,16.84 v1(74.86,16.01)
  BOTTOM w0.203: v1(74.86,16.01) 74.68,15.82 71.81,15.82 68.22,12.24 66.42,12.24 65.28,13.39 65.28,28.24 58.8,34.72 54.94,34.72 52.48,32.26 v1(52.48,29.95)
CLKIN_32: length 12.6
  TOP w0.203: U1.D6 v2(43.48,21.2) ; R183.2 v1(33.61,23.37)
  L3_SIG w0.127: 41.28,20.82 41.3,20.81 43.09,20.81 v2(43.48,21.2)
  L3_SIG w0.152: v1(33.61,23.37) 34.33,23.37 34.4,23.3 37.32,23.3 39.81,20.82 41.28,20.82
CON_CC1: length 19.2
  TOP w0.203: M1.A5 10.09,33.04 10.28,32.84 v1(10.29,32.84) ; v1(10.79,21.58) 10.79,21.59 11.3,22.1 TP63.1
  L3_SIG w0.203: v1(10.29,32.84) 10.29,32.9 10.94,33.55 11.4,33.55 11.79,33.16 11.79,28.17 9.5,25.88 9.5,23.42 10.79,22.12 v1(10.79,21.58)
  BOTTOM w0.203: D15.2 11.34,21.04 v1(10.79,21.58) 10.79,21.59 10.9,21.69 U36.1
CON_CC2: length 15.8
  TOP w0.203: TP62.1 9.53,22.25 v1(10.06,21.72) ; v1(7.05,31.79) 7.2,31.79 7.2,31.79 M1.B5
  L3_SIG w0.203: v1(7.05,31.79) 6.25,30.99 6.25,28.04 8.64,25.65 8.64,23.14 v1(10.06,21.72)
  BOTTOM w0.203: D14.2 9.81,21.47 v1(10.06,21.72) 10.16,21.72 10.5,22.06 U36.2
CON_DN: length 9.4
  TOP w0.152: M1.A7 9.7,32.04 9.8,31.95 9.87,31.95 10.41,31.41 v1(10.41,31.36) ; M1.B7 8.38,32.79 v1(8.56,32.61) ; FL1.A2 11.34,33.18 v1(11.18,33.02)
  BOTTOM w0.152: v1(11.18,33.02) 11.38,32.82 11.39,32.82 11.68,32.52 11.68,32.1 10.95,31.36 v1(10.41,31.36) 10.41,31.36 10.38,31.33 8.21,31.33 8,31.54 8,32.06 v1(8.56,32.61)
CON_DP: length 6
  TOP w0.152: v1(10.47,32.16) 10.37,32.25 10.17,32.25 10.08,32.34 10.08,32.34 9.97,32.45 9.5,32.45 M1.A6 ; M1.B6 8.16,32.29 8.35,32.11 8.41,32.11 8.56,31.96 v1(8.56,31.89) ; v1(11.18,32.31) 11.25,32.38 11.39,32.38 FL1.A1
  BOTTOM w0.152: v1(8.56,31.89) 8.69,31.75 10.06,31.75 v1(10.47,32.16) 11.02,32.16 v1(11.18,32.31)
CON_RX1_N: length 5.2
  TOP w0.152: M1.B10 8.24,34.29 8.31,34.21 8.33,34.21 8.38,34.16 v1(8.52,34.16) ; v1(10.67,35.05) 10.92,35.05 11.59,34.38 FL1.A5
  BOTTOM w0.152: v1(10.67,35.05) 10.43,35.29 10.08,35.29 9.93,35.14 9.93,34.71 9.54,34.32 9.15,34.32 9,34.16 v1(8.52,34.16)
CON_RX1_P: length 5.3
  TOP w0.152: M1.B11 8.44,34.79 v1(8.52,34.87) ; v1(10.67,35.81) 10.76,35.81 FL1.A6
  BOTTOM w0.152: v1(10.67,35.81) 10.55,35.7 9.92,35.7 9.53,35.31 9.53,34.87 9.37,34.72 9.15,34.72 9,34.87 v1(8.52,34.87)
CON_RX2_N: length 3.7
  TOP w0.152: M1.A10 9.97,30.54 10.05,30.46 10.18,30.46 10.67,29.97 10.67,29.07 11.02,28.71 11.42,28.71 11.49,28.77 FL2.A4
CON_RX2_P: length 3.7
  TOP w0.152: FL2.A3 11.75,28.33 11.64,28.33 11.59,28.27 10.89,28.27 10.26,28.9 10.26,29.8 10.03,30.04 M1.A11
CON_TX1_N: length 2.7
  TOP w0.152: M1.A3 9.5,34.13 10.62,34.13 11.18,33.58 11.79,33.58 FL1.A3
CON_TX1_P: length 2.6
  TOP w0.152: M1.A2 10.79,34.54 11.35,33.98 FL1.A4
CON_TX2_N: length 4.8
  TOP w0.152: M1.B3 8.44,30.79 8.47,30.82 v1(8.47,30.82) ; FL2.A6 11.79,29.61 11.43,29.97 v1(11.18,29.97)
  BOTTOM w0.152: v1(11.18,29.97) 10.95,29.75 10.3,29.75 9.31,30.73 8.56,30.73 v1(8.47,30.82)
CON_TX2_P: length 4.7
  TOP w0.152: v1(8.52,30.11) 8.51,30.11 8.33,30.29 8.25,30.29 8.25,30.29 M1.B2 ; FL2.A5 11.38,29.17 11.34,29.22 v1(11.23,29.22)
  BOTTOM w0.152: v1(8.52,30.11) 8.59,30.18 8.65,30.18 8.81,30.33 9.14,30.33 10.13,29.34 11.11,29.34 v1(11.23,29.22)
CON_VBUS: length 6.6
  TOP w0.203: v1(10.69,30.71) 10.57,30.83 10.19,30.83 9.98,31.04 M1.A9 9.36,31.09 8.96,31.09 8.69,31.35 8.25,31.35 8.22,31.32 8.14,31.32 8.11,31.29 M1.B4 ; v1(10.24,33.6) 10.24,33.6 10.17,33.54 M1.A4 8.36,33.54 8.11,33.79 M1.B9 7.2,33.79 7.2,33.79 v1(7.03,33.79)
  vias: v1(4.06,38.48) v1(4.06,37.72) v1(4.95,38.48) v1(4.95,37.72)
CVDDQ: length 67.6
  TOP w0.203: U1.B6 v2(41.88,21.2)
  TOP w0.508: R184.2 v1(36.08,12.45) ; Y2.4 29.97,25.01 R180.1 C203.1 v1(27.69,25.78)
  L3_SIG w0.508: v1(27.69,25.78) 27.74,25.83 27.74,29.13 30.53,31.93 36.31,31.93 v1(36.58,31.67)
  BOTTOM w0.508: v2(41.88,21.2) 41.77,21.09 C161.1 40.92,21.09 39.79,22.22 C150.2 39.24,22.9 39.24,23.92 E7.1 36.66,24.93 35.56,26.04 35.56,26.04 35.15,26.44 35.15,26.44 35.13,26.47 34.13,26.47 33.32,25.65 27.81,25.65 v1(27.69,25.78) 27.56,25.78 26.8,25.02 26.8,19.6 31.67,14.73 33.27,14.73 ; R186.2 37.13,17.2 36.96,17.02 35.56,17.02 33.27,14.73 ; v1(36.08,12.45) 33.78,12.45 33.27,12.96 33.27,14.73 ; v1(36.58,31.67) 36.79,31.67 37.72,30.73 40.01,30.73 41.66,29.08 R188.2
DAC_OUTA: length 5
  BOTTOM w0.203: U16.1 61.7,47.73 62.1,48.13 64.77,48.13 C4.2 65.92,48 R2.1
DAC_OUTB: length 6.3
  BOTTOM w0.203: U16.16 61.44,48.48 63.38,50.41 C9.2 65.92,50.41 R5.1
DAC_OUTC: length 5
  BOTTOM w0.203: R3.1 65.92,45.59 C5.2 62.11,45.59 61.47,46.23 U16.4
DAC_OUTD: length 6.4
  BOTTOM w0.203: R4.1 65.92,43.3 C8.2 63.25,43.3 61.09,45.47 60.46,45.47 U16.5
DOUT_CH0: length 28
  TOP w0.203: R118.1 45.29,29.13 45.29,31.32 45.43,31.46 v1(45.43,31.5) ; v1(42.07,47.85) 42.04,47.82 42.04,47.62 41.55,47.14 U18.27 39.14,47.14 TP41.1
  L3_SIG w0.152: v1(45.43,31.5) 45.31,31.62 45.22,31.62 42.79,34.05 42.79,36.59 39.34,40.03 39.34,46.58 40.61,47.85 v1(42.07,47.85)
DOUT_CH1: length 29.7
  TOP w0.203: TP42.1 37.44,47.09 38.5,47.09 39.05,47.64 U18.26 41.1,47.64 41.88,48.42 42.65,48.42 v1(42.93,48.69)
  BOTTOM w0.203: v1(42.93,48.69) 42.93,47.62 40.87,45.57 40.87,41.38 44.62,37.63 44.62,33.85 44.47,33.7 44.47,31.11 45.13,30.44 R119.1
DOUT_CH2: length 29.2
  TOP w0.203: TP43.1 38.61,48.14 U18.25 41.06,48.14 41.79,48.87 41.99,48.87 42.39,49.28 v1(42.42,49.28)
  L3_SIG w0.152: v1(42.42,49.28) 42.42,48.22 42.57,48.06 42.57,47.54 42.38,47.34 40.57,47.34 39.67,46.44 39.67,42.45 42.9,39.23 42.9,37.37 44.02,36.25 44.02,34.14 v1(44.08,34.07)
  BOTTOM w0.203: R120.1 v1(44.08,34.07)
DOUT_CH3: length 31.7
  TOP w0.203: TP44.1 37.46,48.64 U18.24 40.96,48.64 41.06,48.73 41.11,48.73 41.66,49.27 v1(41.66,49.4) ; R268.1 46.58,29.18 v1(46.58,31.29)
  L3_SIG w0.152: v1(41.66,49.4) 39.01,46.76 39.01,39.9 42.46,36.45 42.46,33.91 44.92,31.45 44.92,31.29 45.22,30.99 46.28,30.99 v1(46.58,31.29)
EN_LOAD_RES: length 54
  TOP w0.152: v1(56.64,12.95) 57.4,12.95 61.21,9.14 v1(61.21,4.57)
  TOP w0.305: Q9.G 98.37,8.45 97.65,7.74 R342.2 v1(96.9,8.64)
  BOTTOM w0.152: v1(96.9,8.64) 91.82,3.56 62.23,3.56 v1(61.21,4.57)
  BOTTOM w0.203: v1(56.64,12.95) TP20.1 56.6,13.76 R163.1
EN_OTG: length 17.6
  TOP w0.203: R354.2 v1(25.15,44.7) ; U42.4 34.28,35.18 R350.1 35.06,35.17 v1(35.18,35.05)
  L3_SIG w0.203: v1(25.15,44.7) 25.55,44.7 26.07,44.19 26.07,43.4 34.3,35.17 35.06,35.17 v1(35.18,35.05)
EXT_BUSY: length 5.9
  TOP w0.152: R213.2 48.5,7.48 47.88,6.86
EXT_I2C_CS: length 6.5
  TOP w0.152: R236.1 31.7,9.79 30.48,8.57 30.48,5.46 P10.1
EXT_I2C_SCLK: length 157.7
  TOP w0.152: R238.2 34.16,6.86
  TOP w0.203: v1(66.07,41.76) 66.17,41.65 U39.2 ; v1(11.05,24.39) 11.68,25.03 TP33.1
  L3_SIG w0.152: v1(63.83,11.15) 63.17,11.81 63.17,21.12 63.37,21.33 63.37,30.89 65.49,33.01 65.49,41.19 66.06,41.76 v1(66.07,41.76) ; v1(11.05,24.39) 11.05,22.84 12.75,21.13 13.16,21.13 13.92,20.37 13.92,12.33 14.86,11.39 14.86,5.04 17.56,2.34 31.55,2.34 32.77,3.56 32.77,5.46 34.16,6.86
  BOTTOM w0.152: v1(11.05,24.39) 10.87,24.57 10.87,25.35 11.43,25.91 16.93,25.91 20.06,22.78 24.9,22.78 25.91,23.79 25.91,26.29 26.92,27.3 31.75,27.3 32.81,28.36 35.27,28.36 35.69,27.94 36.58,27.94 37.33,28.7 38.36,28.7 R234.2 ; v1(63.83,11.15) 60.93,11.15 51.82,2.03 36.6,2.03 35.31,3.33 35.31,5.61 34.16,6.76 34.16,6.86
  BOTTOM w0.203: v1(11.05,24.39) 11.05,24.38 10.9,24.23 U36.8
EXT_I2C_SDA: length 158.5
  TOP w0.152: P10.3 33.02,6.1 R237.2
  TOP w0.203: U39.3 66.17,41.15 v1(66,40.98) ; v1(10.29,24.38) 9.66,25.01 TP35.1
  L3_SIG w0.152: P10.3 31.85,2.01 17.42,2.01 14.48,4.95 14.48,11.3 13.59,12.19 13.59,20.19 12.98,20.8 12.62,20.8 10.29,23.13 v1(10.29,24.38) ; v1(66,40.98) 66,32.65 63.7,30.35 63.7,21.19 63.5,20.99 63.5,12.45 64.49,11.46 64.49,10.57 v1(63.91,9.98)
  BOTTOM w0.152: R235.2 38.49,29.71 37.81,29.03 37.2,29.03 36.49,28.32 35.77,28.32 35.4,28.69 32.67,28.69 31.61,27.64 26.79,27.64 25.58,26.43 25.58,23.93 24.77,23.11 20.19,23.11 17.07,26.24 11.29,26.24 10.54,25.49 10.54,24.64 v1(10.29,24.38) ; P10.3 34.16,3.96 36.58,1.55 52.01,1.55 60.44,9.98 v1(63.91,9.98)
  BOTTOM w0.203: v1(10.29,24.38) 10.5,24.17 U36.7
EXT_SPI_CS: length 17.2
  TOP w0.152: R223.2 50.6,11.5 52.08,10.02 R357.1 52.07,9.14 52.07,3.68 51.05,2.67 47,2.67 45.87,3.79 45.86,3.79 45.34,4.32
EXT_SPI_INT1: length 22.6
  BOTTOM w0.152: 47.88,4.32 49.15,5.59 49.15,9.14 51.49,11.48 56.72,11.48 58.8,13.56 58.8,14.86 56.59,17.07 55.25,17.07 R161.2
EXT_SPI_INT2: length 8.8
  TOP w0.152: P9.2 49.15,5.59 49.15,9.91 49.55,10.31 R212.2
FSLC0: length 7.9
  TOP w0.152: R185.2 38.1,13.84 38.74,14.48 39.5,14.48 40.51,15.49 40.51,16.64 41.05,17.17 41.88,17.17 U1.B2
  TOP w0.305: R184.1 R185.2
FSLC1: length 5.6
  TOP w0.203: U1.B4 v2(41.88,18.77)
  BOTTOM w0.152: 40.03,17.91 40.18,18.05 40.85,18.05 41.56,18.77 v2(41.88,18.77)
  BOTTOM w0.203: 40.03,17.91 39.32,17.2 R186.1 R187.2
FSLC2: length 9.4
  TOP w0.203: U1.E6 v2(44.28,21.2)
  BOTTOM w0.127: v2(44.28,21.2) 44.72,21.63 44.72,22.73
  BOTTOM w0.152: R189.2 43.54,27.56 43.55,27.56 43.61,27.5 43.71,27.5 43.94,27.27 43.94,26.75 44.22,26.48 44.22,26.2 44.22,25.48 44.72,24.98 44.72,22.73
  BOTTOM w0.203: R188.1 R189.2
IEPE_CH0: length 5
  TOP w0.203: U22.1 R49.2 100.97,71.91 R47.2
IEPE_CH1: length 5
  TOP w0.203: R48.2 R50.2 100.8,50.91 U27.1
IEPE_CH2: length 5
  TOP w0.203: R13.2 100.97,33.4 R15.2 U28.1
IEPE_CH3: length 5
  TOP w0.203: U29.1 R16.2 100.85,12.45 R14.2
INT_N_CTL15: length 4.2
  TOP w0.152: U1.L8 49.53,22.39 49.6,22.45 50.37,22.45 50.59,22.23 51.54,22.23 52.09,21.67 R179.1
LED_GPIO4: length 89.8
  TOP w0.203: R165.1 56.03,16.55 56.04,16.56 v1(56.06,16.56) 56.08,16.58 TP23.1 ; R181.1 v1(9.65,65.29)
  L3_SIG w0.152: v1(56.06,16.56) 55.37,17.25 55.37,19.05 53.95,20.47 53.95,23.96 53.57,24.34 53.57,26.64 51.4,28.81 50.2,28.81 50.13,28.88 45.8,28.88 41.47,33.21 41.47,35.92 37.95,39.44 37.95,57.6 29.35,66.19 13.31,66.19 13.09,66.42 10.78,66.42 v1(9.65,65.29)
LOW_SIDE_CH0: length 22.4
  TOP w0.203: U25.8 113.72,65.62 115.06,66.96 J1.1 D7.2 P1.2 R45.2 R47.1
LOW_SIDE_CH1: length 22.5
  TOP w0.203: U34.8 113.62,57.22 114.94,55.91 J2.1 D9.2 P2.2 R46.2 R48.1
LOW_SIDE_CH2: length 22.6
  TOP w0.203: U43.8 113.75,27.14 115.06,28.45 J3.1 D10.2 P3.2 R11.2 R13.1
LOW_SIDE_CH3: length 24.4
  TOP w0.203: U44.8 113.62,18.71 114.94,17.4 J4.1 D11.2 P4.2 R12.2 R14.1 102.87,12.44 R341.2
LT3092_SIDE_CH0: length 11.5
  TOP w0.203: R43.1 C59.1 98.81,66.2 C63.1 98.54,64.91 R51.1 100.23,63.78 102.07,65.62 U25.1
LT3092_SIDE_CH1: length 9.4
  TOP w0.203: R52.1 98.42,56.66 C64.1 98.69,57.94 C60.1 R44.1 99.83,57.94 103.22,57.94 103.94,57.22 U34.1
LT3092_SIDE_CH2: length 11.3
  TOP w0.203: R9.1 C27.1 98.81,27.69 C31.1 98.54,26.4 R17.1 100.33,25.27 102.19,27.14 U43.1
LT3092_SIDE_CH3: length 9.5
  TOP w0.203: R18.1 98.42,18.15 C32.1 98.69,19.43 C28.1 R10.1 102.99,19.44 103.72,18.71 U44.1
LT3092_SW_CH0: length 110.2
  TOP w0.305: R368.2 U25.6 109.09,64.32 v1(109.08,64.3)
  BOTTOM w0.152: R271.2 58.08,19.26 68.35,8.99 85.7,8.99 88.25,11.54 88.25,15.31 91.14,18.2 104.28,18.2 107.21,21.13 107.21,29.89 108.27,30.95 108.27,63.49 v1(109.08,64.3)
LT3092_SW_CH1: length 101
  TOP w0.152: v1(60.58,13.33) 58.17,13.33 57.71,13.79 56.25,13.79 55.92,13.46 R220.2
  TOP w0.305: v1(108.88,55.88) 108.92,55.92 U34.6 R369.2
  BOTTOM w0.152: v1(108.88,55.88) 108.88,55.79 108.71,55.63 108.71,30.92 107.54,29.76 107.54,21 104.4,17.85 91.26,17.85 88.58,15.18 88.58,11.37 85.88,8.66 68.11,8.66 63.31,13.46 60.71,13.46 v1(60.58,13.33)
LT3092_SW_CH2: length 73.7
  TOP w0.203: R370.2 U43.6 109.02,25.84 v1(108.97,25.78)
  BOTTOM w0.152: R221.2 55.3,18.1 56.83,18.1 59.69,15.24 59.69,13.33 60.2,12.83 60.79,12.83 60.88,12.92 63.38,12.92 67.97,8.33 86.69,8.33 87.88,9.53 89.44,9.53 90.3,10.38 90.3,14.86 92.96,17.52 104.54,17.52 108.46,21.44 108.46,25.27 v1(108.97,25.78)
LT3092_SW_CH3: length 66.7
  TOP w0.152: v1(61.21,12.41) 58.45,12.41 57.4,13.46 56.39,13.46 55.34,12.41 R222.2
  TOP w0.305: v1(108.85,17.41) U44.6 R371.2
  BOTTOM w0.152: v1(61.21,12.41) 63.42,12.41 67.94,7.9 86.89,7.9 88.19,9.19 89.57,9.19 90.63,10.25 90.63,14.72 93.1,17.19 104.34,17.19 104.65,16.89 108.33,16.89 v1(108.85,17.41)
LTC3112_FB: length 8.2
  TOP w0.203: R289.1 R291.2 R290.2 28.58,62.41 28.05,62.94 26.58,62.94 26.42,62.79 R288.1 26.29,62.1 C222.1 24.76,62.1 24.76,62.09 U30.3
LTC3112_RUN: length 84
  TOP w0.203: U30.7 v1(24.66,64.69)
  L3_SIG w0.152: v1(42.93,11.68) 43.79,12.55 47.16,12.55 47.47,12.85 50.64,12.85 51.08,13.29 52.49,13.29 53.42,14.21 53.42,18.95 52.89,19.48 52.89,23.12 52.61,23.4 52.61,27.06 51.19,28.48 50.06,28.48 49.99,28.55 45.66,28.55 41.14,33.07 41.14,35.78 37.62,39.3 37.62,57.46 30.18,64.9 24.87,64.9 v1(24.66,64.69)
  BOTTOM w0.152: v1(42.93,11.68) 43.17,11.68 43.32,11.83 R171.2
  BOTTOM w0.203: R287.1 25.18,65.16 24.88,64.87 24.84,64.87 v1(24.66,64.69)
MB_CLOCK_IN: length 113.4
  TOP w0.203: v1(19.04,89.65) R340.1 R339.1
  L3_SIG w0.152: v1(49.78,82.17) 49.61,81.99 49.61,75.17 49.4,74.97 49.4,74.93 45.8,71.32 45.8,67.62 44.96,66.78 44.96,62.86 41.48,59.39 41.48,52.59 42.97,51.11 43.3,51.11 44.75,49.65 44.75,47.22 43.94,46.41 43.94,43.31 49.06,38.19 49.06,35.78 55.55,29.29 55.55,25.16 56.52,24.19 56.52,21.59 v1(56.01,21.08)
  BOTTOM w0.152: TP22.1 v1(56.01,21.08) 55.62,21.08 R164.1 ; v1(49.78,82.17) 49.28,81.66 48.68,81.66 47.74,82.6 21.71,82.6 19.04,85.27 v1(19.04,89.65)
MB_CLOCK_OUT: length 19.4
  TOP w0.203: R334.2 8.51,85.98 9.02,85.47 9.02,83.31 8.89,83.19 7.72,83.19 D20.2 7.6,83.07 R335.2 6.35,82.04 5.59,81.28 1.4,81.28 1.14,81.03 1.14,77.27 P14.2
MB_HOST: length 102.5
  TOP w0.152: v1(41.78,11.68) 41.78,11.68 41.91,11.68 42.39,12.17 42.39,12.44 R172.2
  TOP w0.203: v1(9.3,67.92) 9.3,68.2 9.52,68.42 R313.2
  TOP w0.305: U3.2 9.53,69.35 R313.2
  L3_SIG w0.152: v1(41.78,11.68) 41.78,11.93 43.23,13.39 46.87,13.39 47.21,13.72 49.96,13.72 51.82,15.59 51.89,15.66 51.89,26.68 50.77,27.81 49.8,27.81 49.72,27.89 45.35,27.89 36.53,36.72 36.53,48.21 35.05,49.68 35.05,58.17 34.04,59.18 26.75,59.18 25.99,58.42 17.27,58.42 17.02,58.17 14.94,58.17 8.64,64.47 8.64,67.26 v1(9.3,67.92)
MB_MODE: length 106.6
  TOP w0.152: U37.1 v1(11.16,88.89)
  TOP w0.203: R330.1 v1(17.03,100.96)
  L3_SIG w0.152: v1(11.16,88.89) 11.16,68.85 13.46,66.55 29.46,66.55 38.32,57.69 38.32,39.65 41.8,36.18 41.8,33.48 45.83,29.45 48.94,29.45 v1(49.43,29.94)
  L3_SIG w0.203: v1(17.03,100.96) 14.22,98.16 14.22,91.95 v1(11.16,88.89)
  BOTTOM w0.152: R162.1 50.38,29.75 50.2,29.94 v1(49.43,29.94) 49.43,30.63 50.17,31.37 TP19.1
MB_OSC_IN: length 9.9
  TOP w0.203: U37.6 10.41,88.89 10.65,89.13 10.65,90.15 11.29,90.79 11.35,90.79 11.36,90.8 12.07,90.8 12.32,91.06 12.32,94.36 12.03,94.65 Y6.3
MB_SLAVE: length 121.1
  TOP w0.152: v1(40.77,11.68) 40.79,11.66 41,11.66 41.35,12.02 R173.2
  TOP w0.203: U33.4 v1(10.35,83)
  L3_SIG w0.152: v1(40.77,11.68) 40.77,10.92 41.22,10.47 41.74,10.47 42.42,11.15 42.42,11.89 43.41,12.88 47.03,12.88 47.33,13.18 50.51,13.18 50.95,13.62 52.36,13.62 53.09,14.35 53.09,18.81 52.53,19.37 52.53,19.71 52.53,23.01 52.28,23.26 52.28,26.92 51.05,28.15 49.92,28.15 49.85,28.22 45.52,28.22 40.81,32.93 40.81,33.16 37.29,36.68 37.29,57.32 34.67,59.94 19.18,59.94 18.16,60.96 14.22,60.96 13.01,62.18 11.4,62.18 8.97,64.61 8.97,66.8 9.86,67.69 9.86,76.46 10.11,76.72 10.11,77.14 10.06,77.19 10.06,81.55 10.03,81.58 10.03,82 10.06,82.03 10.06,82.7 v1(10.35,83)
MCLK: length 9.1
  TOP w0.203: R373.2 34.66,42.16 R375.2 35.19,42.17 37.59,44.58 40.11,44.58 U18.32
MCLK_SEL: length 63.2
  TOP w0.203: R372.1 v1(31.49,50.04)
  L3_SIG w0.152: v1(41.53,11.01) 41.28,11.27 41.28,11.89 43.1,13.72 46.59,13.72 46.97,14.1 46.97,14.44 47.27,14.74 50.3,14.74 51.31,15.75 51.31,22.73 51.56,22.99 51.56,25.65 51.05,26.16 50.98,26.16 49.58,27.56 44.24,27.56 42.04,29.77 42.04,30.73 36.2,36.58 36.2,48.01 34.16,50.04 v1(31.49,50.04)
  BOTTOM w0.152: R219.2 42.29,12.44 42.29,11.3 42,11.01 v1(41.53,11.01)
MDAC_SIGNAL: length 29.2
  TOP w0.203: v1(75.62,98.88) A8.6 73.09,98.88 C193.1 73.02,99.83 TP58.1
  TOP w0.305: U32.7 89.61,96.72 89.41,96.52 89.41,92.08 v1(88.65,91.31) R159.1 ; U20.3 v1(80.45,94.69)
  L3_SIG w0.305: v1(88.65,91.31) 86.68,93.28 81.86,93.28 v1(80.45,94.69) 76.26,98.88 v1(75.62,98.88)
N5V_SUPPLY: length 32.2
  TOP w0.203: R360.1 v1(100.88,74.45)
  TOP w0.305: v1(85.7,94.86) C238.1 86.86,94.86 87.42,95.42 U32.4 ; R364.1 100.51,35.99 v1(100.59,36.07) ; R365.1 v1(100.59,14.94) ; A14.4 94.41,95.42 C234.1 C236.2 v1(92.18,94.99) ; R361.1 100.67,53.54 v1(100.72,53.49) ; C189.1 80.74,99.53 A8.4 ; v1(92.96,90.3) C188.2 C186.1 94.54,90.21 A5.4 ; A7.4 80.14,91.27
  TOP w0.508: v1(82.58,91.32) C15.2 C14.1 80.72,91.27 80.14,91.27 ; v1(82.54,99.56) C214.2 C189.1 ; R311.2 v1(83.31,90.68)
  BOTTOM w0.508: v1(92.18,94.99) 92.42,94.74 102.23,94.74 102.74,95.25 R121.1
  vias: v1(54.56,89.43) v1(54.56,88.47) v1(55.22,89.43) v1(55.22,88.47) v1(97.28,90.04) v1(98.17,90.04)
N_SRST: length 4.9
  TOP w0.203: R196.1 19.94,11.68 21.08,10.54 21.08,8.64 P7.10
OTG_ID: length 53.8
  TOP w0.152: v1(26.67,34.04) 28.07,34.04 29.46,32.64 31.37,32.64 31.61,32.88 U42.1
  TOP w0.203: U42.1 31.61,34.15 31.75,34.29 34.17,34.29 R350.2 34.3,34.16 35.56,34.16 37.21,32.51 37.21,30.75 37.07,30.6 37.07,28.72 TP66.1 37.47,28.29 v1(38.07,27.69) ; U1.C9 v2(42.68,23.6)
  L3_SIG w0.127: v2(42.68,23.6) 42.29,23.99 40.44,23.99 40.43,24
  L3_SIG w0.152: v1(26.67,34.04) 26.16,34.04 25.65,33.53 25.65,32.94 25.36,32.64 25.06,32.64 23.75,31.33 23.75,28.7 21.08,26.04 21.08,24.26 18.29,21.46 12.89,21.46 11.68,22.67 11.68,23.88 12.05,24.24 v1(12.08,24.24)
  L3_SIG w0.203: v1(38.07,27.69) 38.22,27.53 38.22,27.09 38.71,26.59 38.71,25.37 40.08,24 40.43,24
  BOTTOM w0.203: U36.9 v1(12.08,24.24) 12.47,24.64 R79.1
PGA_SCLK: length 3.9
  TOP w0.203: R322.2 v1(73.66,41.4) 73.41,41.65 U39.7
  BOTTOM w0.203: U40.22 72.78,41.72 73.05,41.45 73.61,41.45 v1(73.66,41.4)
PGA_SDA: length 5.8
  TOP w0.203: R321.2 v1(73.66,40.26) 73.66,40.57 73.07,41.15 U39.6
  BOTTOM w0.203: v1(73.66,40.26) 73.15,40.26 72.13,41.28 U40.23
PMODE0: length 19.3
  TOP w0.152: v1(46.25,2.54) 46.76,2.03 51.41,2.03 52.8,3.42 R192.1
  BOTTOM w0.152: R168.2 47.5,12.43 47.5,11.95 47.44,11.89 47.44,8.84 46.74,8.13 46.74,3.02 v1(46.25,2.54)
PMODE1: length 18.6
  TOP w0.152: v1(58.29,14.6) 61.34,14.6 61.77,14.17 61.77,5.54 62.36,4.95 64.08,4.95 S1.1A
  BOTTOM w0.152: R169.2 57.24,15.96 58.29,14.9 v1(58.29,14.6)
PMODE2: length 16.7
  TOP w0.152: R170.2 60.95,15.5 62.1,14.35 62.1,8.13 62.73,7.5 S1.2A
PORT_SEL: length 15.6
  TOP w0.203: R114.1 12.33,22.79 v1(12.29,22.79)
  L3_SIG w0.203: v1(12.29,22.79) 12.5,22.79 13.74,24.03 18.18,24.03 21.21,27.06 v1(21.21,27.69)
  BOTTOM w0.152: v1(21.21,27.69) 21.21,27.71 21.06,27.87 U35.12
  BOTTOM w0.203: U36.11 v1(12.29,22.79) R1.1
REF_BUF_EN: length 57.5
  TOP w0.152: A6.5 v1(55.62,57.66) ; R269.1 54.36,19.56 v1(58.62,19.56) ; A9.5 v1(51.16,65.28)
  L3_SIG w0.152: v1(58.62,19.56) 59.28,20.22 59.28,23.24 58.12,24.41 58.12,29.6 56.08,31.63 56.08,38.56 53.09,41.55 53.09,44.17 53.59,44.68 53.59,49.02 55.12,50.55 55.12,57.16 v1(55.62,57.66) 54.89,58.39 54.89,61.54 v1(51.16,65.28)
RESERVED1: length 3.9
  BOTTOM w0.152: R122.1 47.23,30.53 47.12,30.65 47.12,32.32 TP27.1
RESERVED2: length 3.1
  BOTTOM w0.152: TP67.1 45.97,31.88 45.97,30.23 46.18,30.02 R123.1
RESERVED3: length 2.1
  TOP w0.203: TP68.1 49.66,30.46 49.96,30.16 49.96,29.72 49.95,29.71 49.95,29.64 49.53,29.22 R124.1
RESERVED4: length 2.9
  BOTTOM w0.152: R125.1 49.02,29.39 49.02,29.62 48.39,30.25 48.39,30.69 49.02,31.33 TP69.1
RESERVED5: length 1.6
  BOTTOM w0.152: TP71.1 55.49,24.51 R145.1
RTCK: length 5
  TOP w0.203: P7.7 22.86,9.4 22.86,11.69 R205.1
RX1_N: length 13.9
  TOP w0.152: v1(13.72,35.05) 13.46,35.05 12.79,34.38 FL1.C5
  L3_SIG w0.152: v1(18.92,26.29) 18.92,27.15 18.39,27.69 18.39,29.04 15.72,31.71 15.72,34.38 14.94,35.15 13.82,35.15 v1(13.72,35.05)
  BOTTOM w0.152: U35.16 19.1,26.47 v1(18.92,26.29)
RX1_P: length 15
  TOP w0.152: FL1.C6 13.62,35.81 v1(13.72,35.81)
  L3_SIG w0.152: v1(13.72,35.81) 13.97,35.56 15.11,35.56 16.13,34.54 16.13,31.88 18.8,29.21 18.8,27.86 19.33,27.32 19.33,26.9 19.68,26.54 v1(19.68,26.29)
  BOTTOM w0.152: U35.15 19.51,26.96 19.51,26.46 v1(19.68,26.29)
RX2_N: length 9.7
  TOP w0.152: FL2.C4 v1(13.53,28.77)
  BOTTOM w0.152: U35.1 18.59,27.06 12.71,27.06 12.32,27.45 12.32,28.39 12.71,28.77 v1(13.53,28.77)
RX2_P: length 8.4
  TOP w0.152: v1(13.46,28.07) 13.21,28.07 12.91,28.37 12.6,28.37 FL2.C3
  BOTTOM w0.152: v1(13.46,28.07) 13.21,28.32 12.83,28.32 12.73,28.22 12.73,27.62 12.88,27.47 U35.2
RXVDDQ: length 7.4
  TOP w0.203: U1.A2 40.63,17.59 40.54,17.5
  TOP w0.305: 39.94,16.9 40.54,17.5
  TOP w0.508: 39.94,16.9 39.16,16.12 C198.1 38.31,16.29 C195.2 36.53,16.34 E8.1
SPI_CLK: length 170.1
  TOP w0.152: U18.17 39.08,52.14 v1(38.83,52.39)
  TOP w0.203: v1(57.02,41.96) 57.02,41.91 57.28,41.66 R203.1 ; U20.1 77.51,93.39 76.45,92.33 76.45,87.05 76.83,86.67 76.84,84.02 77.16,83.69 v1(77.72,83.69) 77.96,83.45 U19.7 ; v1(40.26,64.52) 40.65,64.91 U12.7
  L3_SIG w0.152: v1(57.02,41.96) 57.12,42.06 57.12,44.11 56.13,45.1 v1(56.13,48.89) 56.13,53.47 58.72,56.06 58.72,71.34 69.17,81.79 72.64,81.79 74.68,83.82 77.59,83.82 v1(77.72,83.69) ; 40.26,6.86 42.43,9.03 42.43,9.21 43.28,10.06 55.96,10.06 59.82,13.92 59.82,17.55 60.6,18.33 60.6,23.79 59.44,24.96 59.44,30.15 57.58,32 57.58,38.94 55.37,41.15 55.37,41.83 55.84,42.3 56.69,42.3 56.92,42.06
  L3_SIG w0.203: 56.92,42.06 v1(57.02,41.96)
  BOTTOM w0.152: U16.10 56.85,46.73 56.64,46.93 56.64,48.01 56.13,48.51 v1(56.13,48.89) 56.13,49.4 55.09,50.44 48.62,50.44 47.6,51.46 39.76,51.46 v1(38.83,52.39) 38.58,52.64 38.58,53.7 40.39,55.5 40.39,64.13 40.26,64.25 v1(40.26,64.52) ; 40.26,6.86 40.26,8.76 TP34.1 40.94,10.36 40.94,11.14 41.28,11.47 41.28,12.4 R174.2
SPI_CLK_FLASH: length 6.9
  TOP w0.203: R203.2 57.28,38.61 55.75,37.08 U2.6 R211.1
SPI_MISO: length 127.4
  TOP w0.152: 42.8,4.32 41.4,5.71 41.4,7.87 39.24,10.03 TP26.1 39.25,10.93 R176.2
  TOP w0.203: U18.19 39.16,51.14 38.36,51.94 v1(36.7,51.94) ; v1(55.12,42.98) 59.4,42.98 59.61,42.77 R202.1 ; v1(39.75,64.01) 40.01,63.75 41.14,63.75 41.55,64.17 41.55,64.47 41.65,64.57 U12.9
  L3_SIG w0.152: v1(55.12,42.98) 55.04,42.98 54.52,42.45 54.52,41.06 56.9,38.68 56.9,31.76 58.78,29.88 58.78,24.68 59.94,23.51 59.94,18.61 59.16,17.82 59.16,14.19 55.71,10.74 43,10.74 41.61,9.35 40.85,9.35 39.12,7.62 39.12,6.1 39.62,5.59 41.53,5.59 42.8,4.32
  BOTTOM w0.152: v1(39.75,64.01) 39.75,56.34 38.36,54.96 38.36,54.47 36.7,52.81 v1(36.7,51.94) 37.72,50.93 42.55,50.93 46.99,46.48 49.02,46.48 49.4,46.1 50.73,46.1 53.38,43.45 54.59,43.45 55.07,42.98 v1(55.12,42.98) 55.17,42.98 55.35,43.15 60.63,43.15 60.78,43.31 60.78,44.03 59.95,44.86 U16.6
